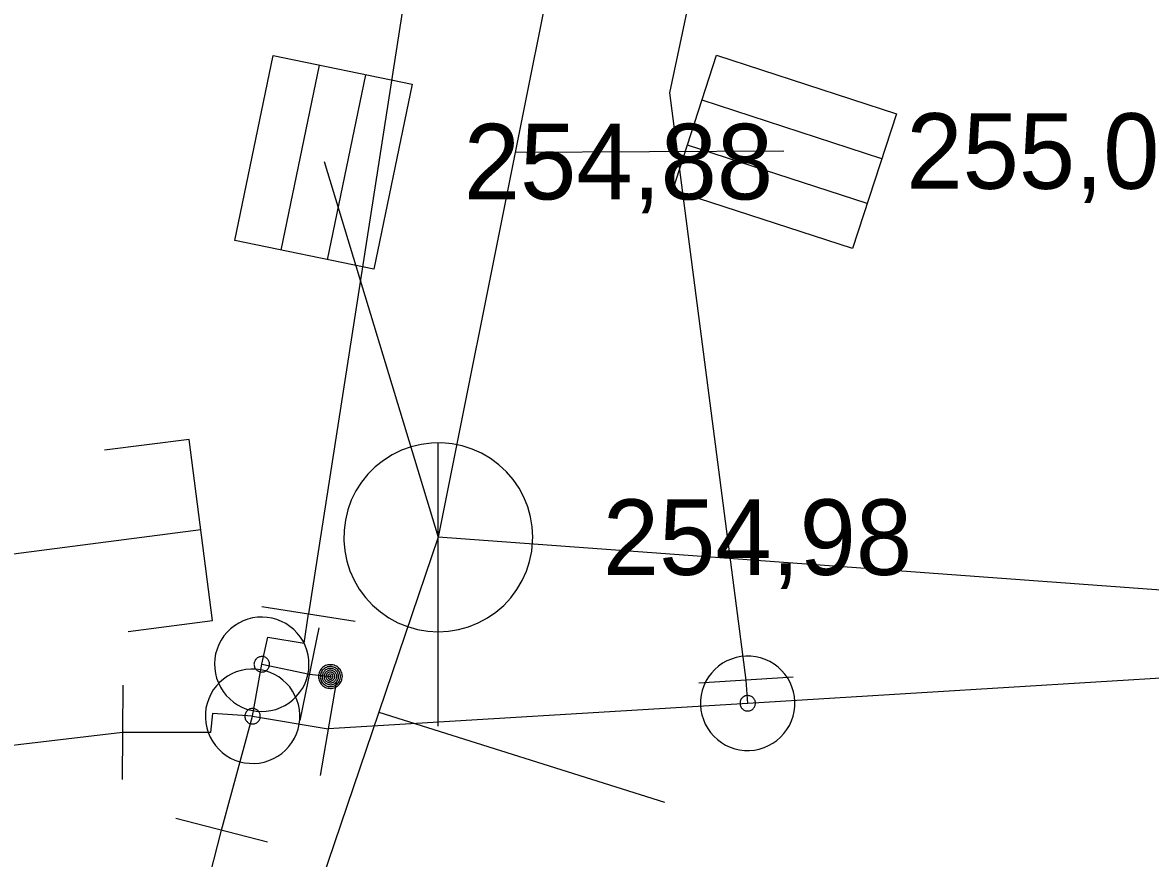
# Model space of a CAD drawing. Extents: x -725807 to -725723.1, y -978165.9 to -978101.2.
# Drawn here: x -725752.81 to -725740.87, y -978127.02 to -978118.17 of the extents above; entities that cross this region are included whole.
import ezdxf

# ---------------------------------------------------------------- set-up
doc = ezdxf.new("R2010")
doc.units = 0
for name, color, linetype in [('Vrstva 1', 7, 'Continuous'), ('Vrstva 11', 7, 'Continuous'), ('Vrstva 14', 7, 'Continuous'), ('Vrstva 17', 7, 'Continuous'), ('Vrstva 22', 7, 'Continuous'), ('Vrstva 31', 7, 'Continuous'), ('Vrstva 34', 7, 'Continuous'), ('Vrstva 47', 7, 'Continuous'), ('Vrstva 9', 7, 'Continuous')]:
    doc.layers.add(name, color=color, linetype=linetype)

msp = doc.modelspace()

# ---------------------------------------------------------------- linework, layer by layer
at = {"layer": 'Vrstva 11'}
for points in [[(-725744.754, -978119.532), (-725747.596, -978119.549)], [(-725749.615, -978119.644), (-725748.41, -978123.62)], [(-725749.038, -978125.47), (-725746.015, -978126.425)]]:
    msp.add_lwpolyline(points, dxfattribs=at)
at = {"layer": 'Vrstva 14'}
for points in [[(-725744.011, -978101.673), (-725744.238, -978102.778), (-725747.596, -978119.549), (-725748.41, -978123.62)], [(-725750.922, -978123.543), (-725758.582, -978124.535), (-725766.42, -978131.467)], [(-725748.41, -978123.62), (-725749.038, -978125.47), (-725751.66, -978133.208)], [(-725735.954, -978124.533), (-725748.41, -978123.62)], [(-725750.277, -978124.965), (-725750.212, -978124.677), (-725749.829, -978124.741), (-725749.783, -978124.431)], [(-725750.374, -978125.515), (-725750.277, -978124.965)], [(-725750.277, -978124.965), (-725749.773, -978125.07)], [(-725749.773, -978125.07), (-725749.55, -978125.094)], [(-725745.136, -978125.378), (-725745.153, -978125.134)], [(-725750.374, -978125.515), (-725750.796, -978125.486), (-725750.82, -978125.688), (-725751.75, -978125.685)], [(-725750.374, -978125.515), (-725749.574, -978125.649)]]:
    msp.add_lwpolyline(points, dxfattribs=at)
at = {"layer": 'Vrstva 17'}
for points in [[(-725746.019, -978101.723), (-725746.838, -978105.504), (-725749.783, -978124.431)], [(-725745.153, -978125.134), (-725745.96, -978118.916), (-725744.074, -978110.021), (-725743.956, -978109.377), (-725741.974, -978101.623)], [(-725725.684, -978125.879), (-725730.408, -978124.478), (-725745.136, -978125.378)], [(-725745.136, -978125.378), (-725749.574, -978125.649)], [(-725750.701, -978126.719), (-725750.374, -978125.515)], [(-725751.75, -978125.685), (-725754.02, -978125.954)], [(-725748.949, -978163.767), (-725749.477, -978157.465), (-725752.379, -978133.28), (-725750.701, -978126.719)]]:
    msp.add_lwpolyline(points, dxfattribs=at)
at = {"layer": 'Vrstva 22'}
for points in [[(-725750.56, -978120.48), (-725750.155, -978118.522), (-725748.686, -978118.826), (-725749.091, -978120.784), (-725750.56, -978120.48)], [(-725744.026, -978120.564), (-725745.928, -978119.945), (-725745.464, -978118.519), (-725743.562, -978119.137), (-725744.026, -978120.564)], [(-725750.07, -978120.582), (-725749.665, -978118.623)], [(-725749.581, -978120.683), (-725749.176, -978118.724)], [(-725743.717, -978119.613), (-725745.619, -978118.994)], [(-725743.871, -978120.088), (-725745.773, -978119.469)], [(-725747.41, -978123.62), (-725747.415, -978123.511), (-725747.433, -978123.403), (-725747.463, -978123.297), (-725747.503, -978123.196), (-725747.555, -978123.099), (-725747.617, -978123.009), (-725747.689, -978122.926), (-725747.769, -978122.852), (-725747.857, -978122.786), (-725747.951, -978122.731), (-725748.051, -978122.686), (-725748.156, -978122.653), (-725748.263, -978122.631), (-725748.372, -978122.621), (-725748.482, -978122.623), (-725748.59, -978122.637), (-725748.697, -978122.662), (-725748.8, -978122.699), (-725748.898, -978122.748), (-725748.99, -978122.806), (-725749.076, -978122.875), (-725749.153, -978122.952), (-725749.222, -978123.038), (-725749.281, -978123.13), (-725749.329, -978123.228), (-725749.366, -978123.331), (-725749.392, -978123.438), (-725749.406, -978123.546), (-725749.409, -978123.656), (-725749.399, -978123.765), (-725749.378, -978123.872), (-725749.344, -978123.976), (-725749.3, -978124.076), (-725749.245, -978124.171), (-725749.179, -978124.259), (-725749.105, -978124.339), (-725749.022, -978124.411), (-725748.932, -978124.473), (-725748.836, -978124.525), (-725748.734, -978124.566), (-725748.629, -978124.596), (-725748.521, -978124.614), (-725748.411, -978124.62), (-725748.302, -978124.614), (-725748.194, -978124.596), (-725748.089, -978124.567), (-725747.987, -978124.526), (-725747.89, -978124.474), (-725747.8, -978124.412), (-725747.717, -978124.341), (-725747.642, -978124.261), (-725747.577, -978124.173), (-725747.521, -978124.079), (-725747.477, -978123.979), (-725747.443, -978123.875), (-725747.421, -978123.767), (-725747.411, -978123.658), (-725747.41, -978123.62)], [(-725748.41, -978125.62), (-725748.409, -978122.62)]]:
    msp.add_lwpolyline(points, dxfattribs=at)
at = {"layer": 'Vrstva 31'}
for points in [[(-725751.045, -978122.584), (-725751.939, -978122.7)], [(-725750.797, -978124.5), (-725751.045, -978122.584)], [(-725751.69, -978124.616), (-725750.797, -978124.5)]]:
    msp.add_lwpolyline(points, dxfattribs=at)
at = {"layer": 'Vrstva 34'}
for points in [[(-725750.277, -978124.354), (-725749.289, -978124.508)], [(-725749.673, -978124.58), (-725749.873, -978125.559)], [(-725744.654, -978125.1), (-725745.651, -978125.166)], [(-725751.748, -978125.185), (-725751.752, -978126.184)], [(-725749.49, -978125.156), (-725749.658, -978126.141)], [(-725751.185, -978126.595), (-725750.216, -978126.843)]]:
    msp.add_lwpolyline(points, dxfattribs=at)
at = {"layer": 'Vrstva 47'}
for points in [[(-725750.231, -978125.462), (-725750.179, -978125.455), (-725750.128, -978125.442), (-725750.08, -978125.423), (-725750.033, -978125.401), (-725749.988, -978125.373), (-725749.947, -978125.34), (-725749.91, -978125.303), (-725749.877, -978125.263), (-725749.847, -978125.22), (-725749.822, -978125.174), (-725749.803, -978125.125), (-725749.789, -978125.075), (-725749.78, -978125.023), (-725749.777, -978124.971), (-725749.779, -978124.919), (-725749.786, -978124.867), (-725749.799, -978124.816), (-725749.818, -978124.767), (-725749.84, -978124.721), (-725749.868, -978124.676), (-725749.901, -978124.635), (-725749.938, -978124.597), (-725749.978, -978124.564), (-725750.021, -978124.534), (-725750.067, -978124.51), (-725750.116, -978124.491), (-725750.167, -978124.476), (-725750.218, -978124.468), (-725750.27, -978124.465), (-725750.322, -978124.467), (-725750.374, -978124.474), (-725750.425, -978124.487), (-725750.474, -978124.505), (-725750.52, -978124.528), (-725750.565, -978124.556), (-725750.606, -978124.588), (-725750.644, -978124.625), (-725750.678, -978124.665), (-725750.707, -978124.709), (-725750.731, -978124.755), (-725750.75, -978124.804), (-725750.765, -978124.854), (-725750.773, -978124.906), (-725750.776, -978124.958), (-725750.774, -978125.01), (-725750.767, -978125.062), (-725750.754, -978125.113), (-725750.736, -978125.161), (-725750.713, -978125.208), (-725750.685, -978125.253), (-725750.653, -978125.294), (-725750.616, -978125.331), (-725750.576, -978125.365), (-725750.532, -978125.394), (-725750.486, -978125.419), (-725750.437, -978125.438), (-725750.388, -978125.452), (-725750.335, -978125.461), (-725750.283, -978125.464), (-725750.231, -978125.462)], [(-725750.269, -978125.046), (-725750.26, -978125.045), (-725750.252, -978125.043), (-725750.244, -978125.04), (-725750.237, -978125.036), (-725750.229, -978125.031), (-725750.223, -978125.026), (-725750.216, -978125.02), (-725750.211, -978125.014), (-725750.206, -978125.006), (-725750.202, -978124.999), (-725750.199, -978124.991), (-725750.197, -978124.982), (-725750.195, -978124.974), (-725750.194, -978124.966), (-725750.195, -978124.957), (-725750.196, -978124.948), (-725750.198, -978124.94), (-725750.201, -978124.932), (-725750.205, -978124.925), (-725750.21, -978124.917), (-725750.215, -978124.911), (-725750.221, -978124.904), (-725750.227, -978124.899), (-725750.235, -978124.893), (-725750.242, -978124.89), (-725750.25, -978124.887), (-725750.259, -978124.885), (-725750.267, -978124.883), (-725750.275, -978124.882), (-725750.284, -978124.883), (-725750.293, -978124.884), (-725750.301, -978124.886), (-725750.309, -978124.889), (-725750.316, -978124.893), (-725750.324, -978124.898), (-725750.33, -978124.902), (-725750.337, -978124.909), (-725750.342, -978124.915), (-725750.348, -978124.923), (-725750.351, -978124.93), (-725750.354, -978124.938), (-725750.356, -978124.947), (-725750.358, -978124.955), (-725750.359, -978124.963), (-725750.358, -978124.972), (-725750.357, -978124.981), (-725750.355, -978124.989), (-725750.352, -978124.997), (-725750.348, -978125.004), (-725750.343, -978125.012), (-725750.339, -978125.018), (-725750.332, -978125.025), (-725750.326, -978125.03), (-725750.318, -978125.035), (-725750.311, -978125.039), (-725750.303, -978125.042), (-725750.294, -978125.044), (-725750.286, -978125.046), (-725750.278, -978125.047), (-725750.269, -978125.046)], [(-725744.687, -978125.157), (-725744.712, -978125.112), (-725744.742, -978125.068), (-725744.777, -978125.03), (-725744.815, -978124.994), (-725744.857, -978124.962), (-725744.903, -978124.935), (-725744.95, -978124.914), (-725744.999, -978124.897), (-725745.05, -978124.885), (-725745.102, -978124.879), (-725745.155, -978124.878), (-725745.207, -978124.883), (-725745.258, -978124.893), (-725745.308, -978124.909), (-725745.356, -978124.929), (-725745.401, -978124.954), (-725745.445, -978124.984), (-725745.484, -978125.02), (-725745.519, -978125.057), (-725745.551, -978125.099), (-725745.578, -978125.145), (-725745.6, -978125.192), (-725745.617, -978125.242), (-725745.629, -978125.292), (-725745.634, -978125.344), (-725745.635, -978125.397), (-725745.631, -978125.449), (-725745.62, -978125.5), (-725745.604, -978125.55), (-725745.584, -978125.598), (-725745.559, -978125.643), (-725745.529, -978125.687), (-725745.494, -978125.727), (-725745.456, -978125.761), (-725745.414, -978125.793), (-725745.369, -978125.82), (-725745.322, -978125.842), (-725745.272, -978125.859), (-725745.221, -978125.871), (-725745.169, -978125.876), (-725745.116, -978125.877), (-725745.065, -978125.873), (-725745.013, -978125.862), (-725744.963, -978125.846), (-725744.915, -978125.826), (-725744.87, -978125.801), (-725744.826, -978125.771), (-725744.787, -978125.737), (-725744.752, -978125.698), (-725744.72, -978125.656), (-725744.693, -978125.611), (-725744.672, -978125.564), (-725744.655, -978125.515), (-725744.643, -978125.463), (-725744.637, -978125.411), (-725744.636, -978125.358), (-725744.641, -978125.307), (-725744.651, -978125.255), (-725744.667, -978125.205), (-725744.687, -978125.157)], [(-725749.925, -978125.294), (-725749.95, -978125.249), (-725749.98, -978125.205), (-725750.015, -978125.167), (-725750.053, -978125.131), (-725750.095, -978125.099), (-725750.141, -978125.072), (-725750.188, -978125.051), (-725750.237, -978125.034), (-725750.288, -978125.022), (-725750.34, -978125.016), (-725750.393, -978125.015), (-725750.445, -978125.02), (-725750.496, -978125.03), (-725750.546, -978125.046), (-725750.594, -978125.066), (-725750.639, -978125.091), (-725750.683, -978125.121), (-725750.722, -978125.157), (-725750.757, -978125.194), (-725750.789, -978125.236), (-725750.816, -978125.282), (-725750.838, -978125.329), (-725750.855, -978125.379), (-725750.867, -978125.429), (-725750.872, -978125.481), (-725750.873, -978125.534), (-725750.869, -978125.586), (-725750.858, -978125.637), (-725750.842, -978125.687), (-725750.822, -978125.735), (-725750.797, -978125.78), (-725750.767, -978125.824), (-725750.732, -978125.864), (-725750.694, -978125.898), (-725750.652, -978125.93), (-725750.607, -978125.957), (-725750.56, -978125.979), (-725750.51, -978125.996), (-725750.459, -978126.008), (-725750.407, -978126.013), (-725750.354, -978126.014), (-725750.303, -978126.01), (-725750.251, -978125.999), (-725750.201, -978125.983), (-725750.153, -978125.963), (-725750.108, -978125.938), (-725750.064, -978125.908), (-725750.025, -978125.874), (-725749.99, -978125.835), (-725749.958, -978125.793), (-725749.931, -978125.748), (-725749.91, -978125.701), (-725749.893, -978125.652), (-725749.881, -978125.6), (-725749.875, -978125.548), (-725749.874, -978125.495), (-725749.879, -978125.444), (-725749.889, -978125.392), (-725749.905, -978125.342), (-725749.925, -978125.294)], [(-725745.062, -978125.341), (-725745.066, -978125.333), (-725745.071, -978125.327), (-725745.077, -978125.321), (-725745.083, -978125.315), (-725745.09, -978125.309), (-725745.097, -978125.305), (-725745.105, -978125.301), (-725745.113, -978125.298), (-725745.122, -978125.297), (-725745.13, -978125.296), (-725745.139, -978125.296), (-725745.147, -978125.296), (-725745.156, -978125.298), (-725745.164, -978125.3), (-725745.172, -978125.304), (-725745.18, -978125.308), (-725745.186, -978125.313), (-725745.192, -978125.319), (-725745.198, -978125.325), (-725745.204, -978125.332), (-725745.208, -978125.339), (-725745.212, -978125.347), (-725745.215, -978125.355), (-725745.217, -978125.364), (-725745.217, -978125.372), (-725745.217, -978125.381), (-725745.217, -978125.389), (-725745.215, -978125.398), (-725745.213, -978125.406), (-725745.209, -978125.414), (-725745.205, -978125.422), (-725745.2, -978125.428), (-725745.194, -978125.434), (-725745.188, -978125.44), (-725745.181, -978125.446), (-725745.174, -978125.45), (-725745.166, -978125.454), (-725745.158, -978125.457), (-725745.149, -978125.459), (-725745.141, -978125.459), (-725745.132, -978125.459), (-725745.124, -978125.459), (-725745.115, -978125.457), (-725745.107, -978125.455), (-725745.099, -978125.451), (-725745.091, -978125.447), (-725745.085, -978125.442), (-725745.079, -978125.436), (-725745.073, -978125.43), (-725745.067, -978125.423), (-725745.063, -978125.416), (-725745.059, -978125.408), (-725745.056, -978125.4), (-725745.055, -978125.391), (-725745.054, -978125.383), (-725745.054, -978125.374), (-725745.054, -978125.366), (-725745.056, -978125.357), (-725745.058, -978125.349), (-725745.062, -978125.341)], [(-725750.3, -978125.478), (-725750.304, -978125.47), (-725750.309, -978125.464), (-725750.315, -978125.458), (-725750.321, -978125.452), (-725750.328, -978125.446), (-725750.335, -978125.442), (-725750.343, -978125.438), (-725750.351, -978125.435), (-725750.36, -978125.434), (-725750.368, -978125.433), (-725750.377, -978125.433), (-725750.385, -978125.433), (-725750.394, -978125.435), (-725750.402, -978125.437), (-725750.41, -978125.441), (-725750.418, -978125.445), (-725750.424, -978125.45), (-725750.43, -978125.456), (-725750.436, -978125.462), (-725750.442, -978125.469), (-725750.446, -978125.476), (-725750.45, -978125.484), (-725750.453, -978125.492), (-725750.455, -978125.501), (-725750.455, -978125.509), (-725750.455, -978125.518), (-725750.455, -978125.526), (-725750.453, -978125.535), (-725750.451, -978125.543), (-725750.447, -978125.551), (-725750.443, -978125.559), (-725750.438, -978125.565), (-725750.432, -978125.571), (-725750.426, -978125.577), (-725750.419, -978125.583), (-725750.412, -978125.587), (-725750.404, -978125.591), (-725750.396, -978125.594), (-725750.387, -978125.596), (-725750.379, -978125.596), (-725750.37, -978125.596), (-725750.362, -978125.596), (-725750.353, -978125.594), (-725750.345, -978125.592), (-725750.337, -978125.588), (-725750.329, -978125.584), (-725750.323, -978125.579), (-725750.317, -978125.573), (-725750.311, -978125.567), (-725750.305, -978125.56), (-725750.301, -978125.553), (-725750.297, -978125.545), (-725750.294, -978125.537), (-725750.293, -978125.528), (-725750.292, -978125.52), (-725750.292, -978125.511), (-725750.292, -978125.503), (-725750.294, -978125.494), (-725750.296, -978125.486), (-725750.3, -978125.478)]]:
    msp.add_lwpolyline(points, dxfattribs=at)
at = {"layer": 'Vrstva 9'}
for points in [[(-725749.676, -978125.094), (-725749.676, -978125.107), (-725749.674, -978125.12), (-725749.671, -978125.133), (-725749.666, -978125.145), (-725749.66, -978125.157), (-725749.653, -978125.168), (-725749.645, -978125.178), (-725749.635, -978125.188), (-725749.625, -978125.196), (-725749.614, -978125.203), (-725749.602, -978125.209), (-725749.59, -978125.214), (-725749.577, -978125.217), (-725749.564, -978125.219), (-725749.551, -978125.221), (-725749.538, -978125.22), (-725749.525, -978125.218), (-725749.512, -978125.215), (-725749.5, -978125.21), (-725749.488, -978125.204), (-725749.477, -978125.197), (-725749.467, -978125.189), (-725749.457, -978125.179), (-725749.449, -978125.169), (-725749.442, -978125.158), (-725749.436, -978125.146), (-725749.431, -978125.134), (-725749.428, -978125.121), (-725749.426, -978125.108), (-725749.424, -978125.095), (-725749.425, -978125.082), (-725749.427, -978125.069), (-725749.43, -978125.056), (-725749.435, -978125.044), (-725749.441, -978125.032), (-725749.448, -978125.021), (-725749.456, -978125.011), (-725749.466, -978125.001), (-725749.476, -978124.993), (-725749.487, -978124.986), (-725749.499, -978124.98), (-725749.511, -978124.975), (-725749.524, -978124.972), (-725749.537, -978124.97), (-725749.55, -978124.969), (-725749.563, -978124.969), (-725749.576, -978124.971), (-725749.589, -978124.974), (-725749.601, -978124.979), (-725749.613, -978124.985), (-725749.624, -978124.992), (-725749.634, -978125), (-725749.644, -978125.01), (-725749.652, -978125.02), (-725749.659, -978125.031), (-725749.665, -978125.043), (-725749.67, -978125.055), (-725749.673, -978125.068), (-725749.675, -978125.081), (-725749.676, -978125.094)], [(-725749.656, -978125.094), (-725749.657, -978125.105), (-725749.655, -978125.116), (-725749.652, -978125.127), (-725749.648, -978125.137), (-725749.643, -978125.147), (-725749.637, -978125.156), (-725749.63, -978125.165), (-725749.622, -978125.173), (-725749.613, -978125.18), (-725749.604, -978125.186), (-725749.594, -978125.191), (-725749.584, -978125.195), (-725749.573, -978125.198), (-725749.562, -978125.201), (-725749.551, -978125.201), (-725749.54, -978125.201), (-725749.529, -978125.199), (-725749.518, -978125.196), (-725749.508, -978125.192), (-725749.498, -978125.187), (-725749.489, -978125.181), (-725749.48, -978125.174), (-725749.472, -978125.166), (-725749.465, -978125.157), (-725749.459, -978125.148), (-725749.454, -978125.138), (-725749.45, -978125.128), (-725749.447, -978125.117), (-725749.445, -978125.106), (-725749.444, -978125.095), (-725749.444, -978125.084), (-725749.446, -978125.073), (-725749.449, -978125.062), (-725749.453, -978125.052), (-725749.458, -978125.042), (-725749.464, -978125.033), (-725749.471, -978125.024), (-725749.479, -978125.016), (-725749.488, -978125.009), (-725749.497, -978125.003), (-725749.507, -978124.998), (-725749.517, -978124.994), (-725749.528, -978124.991), (-725749.539, -978124.989), (-725749.55, -978124.989), (-725749.561, -978124.988), (-725749.572, -978124.99), (-725749.583, -978124.993), (-725749.593, -978124.997), (-725749.603, -978125.002), (-725749.612, -978125.008), (-725749.621, -978125.015), (-725749.629, -978125.023), (-725749.636, -978125.032), (-725749.642, -978125.041), (-725749.647, -978125.051), (-725749.651, -978125.061), (-725749.654, -978125.072), (-725749.656, -978125.083), (-725749.656, -978125.094)], [(-725749.637, -978125.094), (-725749.637, -978125.103), (-725749.636, -978125.112), (-725749.633, -978125.121), (-725749.63, -978125.129), (-725749.626, -978125.137), (-725749.621, -978125.145), (-725749.615, -978125.152), (-725749.609, -978125.158), (-725749.602, -978125.164), (-725749.594, -978125.169), (-725749.586, -978125.173), (-725749.578, -978125.176), (-725749.569, -978125.179), (-725749.56, -978125.18), (-725749.551, -978125.182), (-725749.542, -978125.181), (-725749.533, -978125.18), (-725749.524, -978125.177), (-725749.516, -978125.174), (-725749.508, -978125.17), (-725749.5, -978125.165), (-725749.493, -978125.159), (-725749.487, -978125.153), (-725749.481, -978125.146), (-725749.476, -978125.138), (-725749.472, -978125.13), (-725749.469, -978125.122), (-725749.466, -978125.113), (-725749.465, -978125.104), (-725749.463, -978125.095), (-725749.464, -978125.086), (-725749.465, -978125.077), (-725749.468, -978125.068), (-725749.471, -978125.06), (-725749.475, -978125.052), (-725749.48, -978125.044), (-725749.486, -978125.037), (-725749.492, -978125.031), (-725749.499, -978125.025), (-725749.507, -978125.02), (-725749.515, -978125.016), (-725749.523, -978125.013), (-725749.532, -978125.01), (-725749.541, -978125.009), (-725749.55, -978125.008), (-725749.559, -978125.008), (-725749.568, -978125.009), (-725749.577, -978125.012), (-725749.585, -978125.015), (-725749.593, -978125.019), (-725749.601, -978125.024), (-725749.608, -978125.03), (-725749.614, -978125.036), (-725749.62, -978125.043), (-725749.625, -978125.051), (-725749.629, -978125.059), (-725749.632, -978125.067), (-725749.635, -978125.076), (-725749.636, -978125.085), (-725749.637, -978125.094)], [(-725749.617, -978125.094), (-725749.617, -978125.101), (-725749.616, -978125.108), (-725749.615, -978125.115), (-725749.612, -978125.121), (-725749.609, -978125.127), (-725749.605, -978125.133), (-725749.601, -978125.139), (-725749.596, -978125.144), (-725749.59, -978125.148), (-725749.584, -978125.152), (-725749.578, -978125.155), (-725749.572, -978125.158), (-725749.565, -978125.159), (-725749.558, -978125.162), (-725749.551, -978125.162), (-725749.544, -978125.162), (-725749.537, -978125.16), (-725749.53, -978125.159), (-725749.524, -978125.156), (-725749.517, -978125.153), (-725749.512, -978125.149), (-725749.506, -978125.145), (-725749.501, -978125.14), (-725749.497, -978125.134), (-725749.493, -978125.128), (-725749.49, -978125.122), (-725749.487, -978125.116), (-725749.485, -978125.109), (-725749.484, -978125.102), (-725749.483, -978125.095), (-725749.483, -978125.088), (-725749.484, -978125.081), (-725749.486, -978125.074), (-725749.489, -978125.068), (-725749.492, -978125.061), (-725749.496, -978125.056), (-725749.5, -978125.05), (-725749.505, -978125.045), (-725749.511, -978125.041), (-725749.516, -978125.037), (-725749.523, -978125.034), (-725749.529, -978125.031), (-725749.536, -978125.029), (-725749.543, -978125.028), (-725749.55, -978125.028), (-725749.557, -978125.028), (-725749.564, -978125.028), (-725749.571, -978125.03), (-725749.577, -978125.033), (-725749.583, -978125.036), (-725749.589, -978125.04), (-725749.595, -978125.044), (-725749.6, -978125.049), (-725749.604, -978125.055), (-725749.608, -978125.06), (-725749.611, -978125.067), (-725749.614, -978125.073), (-725749.615, -978125.08), (-725749.617, -978125.087), (-725749.617, -978125.094)], [(-725749.597, -978125.094), (-725749.597, -978125.099), (-725749.597, -978125.104), (-725749.596, -978125.109), (-725749.594, -978125.113), (-725749.592, -978125.118), (-725749.589, -978125.122), (-725749.586, -978125.125), (-725749.582, -978125.129), (-725749.579, -978125.132), (-725749.575, -978125.135), (-725749.57, -978125.137), (-725749.566, -978125.139), (-725749.561, -978125.14), (-725749.556, -978125.142), (-725749.551, -978125.142), (-725749.546, -978125.142), (-725749.541, -978125.141), (-725749.536, -978125.14), (-725749.532, -978125.138), (-725749.527, -978125.136), (-725749.523, -978125.133), (-725749.519, -978125.13), (-725749.516, -978125.126), (-725749.513, -978125.123), (-725749.51, -978125.119), (-725749.508, -978125.114), (-725749.506, -978125.11), (-725749.505, -978125.105), (-725749.504, -978125.1), (-725749.503, -978125.095), (-725749.503, -978125.09), (-725749.504, -978125.085), (-725749.505, -978125.08), (-725749.507, -978125.076), (-725749.509, -978125.071), (-725749.512, -978125.067), (-725749.515, -978125.063), (-725749.518, -978125.06), (-725749.522, -978125.057), (-725749.526, -978125.054), (-725749.531, -978125.052), (-725749.535, -978125.05), (-725749.54, -978125.049), (-725749.545, -978125.048), (-725749.55, -978125.048), (-725749.555, -978125.048), (-725749.56, -978125.049), (-725749.565, -978125.049), (-725749.569, -978125.051), (-725749.574, -978125.053), (-725749.578, -978125.056), (-725749.581, -978125.059), (-725749.585, -978125.062), (-725749.588, -978125.066), (-725749.591, -978125.07), (-725749.593, -978125.075), (-725749.595, -978125.079), (-725749.596, -978125.084), (-725749.597, -978125.089), (-725749.597, -978125.094)], [(-725749.577, -978125.094), (-725749.577, -978125.097), (-725749.578, -978125.1), (-725749.577, -978125.102), (-725749.576, -978125.105), (-725749.575, -978125.108), (-725749.573, -978125.11), (-725749.571, -978125.112), (-725749.569, -978125.114), (-725749.567, -978125.116), (-725749.565, -978125.118), (-725749.562, -978125.12), (-725749.559, -978125.121), (-725749.557, -978125.121), (-725749.554, -978125.122), (-725749.551, -978125.122), (-725749.548, -978125.122), (-725749.545, -978125.122), (-725749.542, -978125.121), (-725749.54, -978125.12), (-725749.537, -978125.119), (-725749.535, -978125.117), (-725749.532, -978125.115), (-725749.53, -978125.113), (-725749.529, -978125.111), (-725749.527, -978125.109), (-725749.526, -978125.106), (-725749.524, -978125.103), (-725749.524, -978125.101), (-725749.523, -978125.098), (-725749.522, -978125.095), (-725749.523, -978125.092), (-725749.523, -978125.089), (-725749.524, -978125.086), (-725749.525, -978125.084), (-725749.526, -978125.081), (-725749.528, -978125.079), (-725749.529, -978125.076), (-725749.531, -978125.074), (-725749.534, -978125.073), (-725749.536, -978125.071), (-725749.539, -978125.07), (-725749.541, -978125.069), (-725749.544, -978125.068), (-725749.547, -978125.068), (-725749.55, -978125.067), (-725749.553, -978125.068), (-725749.556, -978125.067), (-725749.558, -978125.069), (-725749.561, -978125.069), (-725749.564, -978125.07), (-725749.566, -978125.072), (-725749.568, -978125.073), (-725749.57, -978125.075), (-725749.572, -978125.078), (-725749.574, -978125.08), (-725749.575, -978125.083), (-725749.576, -978125.085), (-725749.577, -978125.088), (-725749.577, -978125.091), (-725749.577, -978125.094)], [(-725749.558, -978125.094), (-725749.558, -978125.096), (-725749.558, -978125.096), (-725749.557, -978125.096), (-725749.557, -978125.098), (-725749.558, -978125.099), (-725749.556, -978125.099), (-725749.556, -978125.099), (-725749.556, -978125.101), (-725749.556, -978125.101), (-725749.555, -978125.102), (-725749.553, -978125.102), (-725749.553, -978125.102), (-725749.553, -978125.103), (-725749.551, -978125.103), (-725749.551, -978125.103), (-725749.55, -978125.103), (-725749.549, -978125.103), (-725749.549, -978125.102), (-725749.548, -978125.102), (-725749.546, -978125.102), (-725749.546, -978125.101), (-725749.546, -978125.101), (-725749.545, -978125.1), (-725749.545, -978125.1), (-725749.543, -978125.099), (-725749.543, -978125.098), (-725749.542, -978125.097), (-725749.542, -978125.097), (-725749.542, -978125.096), (-725749.542, -978125.095), (-725749.542, -978125.094), (-725749.542, -978125.093), (-725749.542, -978125.093), (-725749.543, -978125.092), (-725749.543, -978125.091), (-725749.544, -978125.09), (-725749.544, -978125.09), (-725749.545, -978125.089), (-725749.545, -978125.089), (-725749.546, -978125.088), (-725749.547, -978125.088), (-725749.548, -978125.087), (-725749.548, -978125.087), (-725749.549, -978125.087), (-725749.55, -978125.087), (-725749.551, -978125.087), (-725749.552, -978125.087), (-725749.552, -978125.087), (-725749.553, -978125.088), (-725749.554, -978125.087), (-725749.555, -978125.089), (-725749.555, -978125.089), (-725749.556, -978125.089), (-725749.556, -978125.089), (-725749.557, -978125.091), (-725749.557, -978125.092), (-725749.557, -978125.093), (-725749.558, -978125.093), (-725749.558, -978125.094), (-725749.558, -978125.094)]]:
    msp.add_lwpolyline(points, dxfattribs=at)

# ---------------------------------------------------------------- texts
at = {"layer": 'Vrstva 1'}
for s, p in [('255,05', (-725743.457, -978119.932)), ('254,88', (-725748.139, -978120.044)), ('254,98', (-725746.668, -978124.019))]:
    msp.add_text(s, height=0.8, dxfattribs=at).set_placement(p)

doc.saveas('drawing.dxf')
